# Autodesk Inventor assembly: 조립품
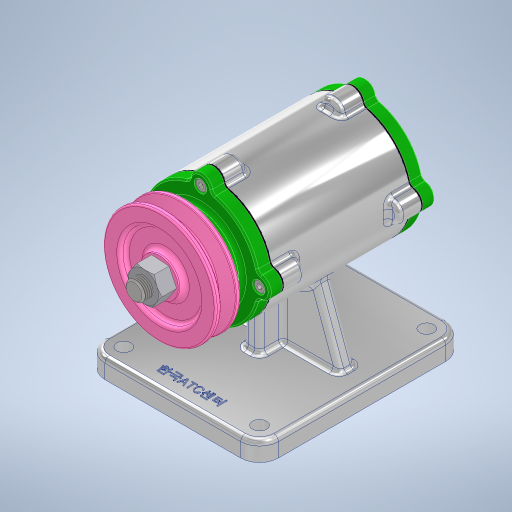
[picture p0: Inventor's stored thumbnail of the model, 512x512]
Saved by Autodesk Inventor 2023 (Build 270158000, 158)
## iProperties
Created: 2023-08
Part Number: 조립품
Document SubType Name: Assembly
Designer: asung
Author: asung
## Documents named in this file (12)
- C:\Users\asung\Desktop\730808V1007\730808V1007\조립품.iam
- C:\Users\asung\Desktop\730808V1007\본체.ipt
- C:\Users\asung\Desktop\730808V1007\730808V1007\앞커버.ipt
- C:\Users\asung\Desktop\730808V1007\730808V1007\뒤커버.ipt
- C:\Users\asung\Desktop\730808V1007\730808V1007\베어링 6204.ipt
- C:\Users\asung\Desktop\730808V1007\730808V1007\개스킷.ipt
- C:\Users\asung\Desktop\730808V1007\730808V1007\오일 실.ipt
- C:\Users\asung\Desktop\730808V1007\730808V1007\축.ipt
- C:\Users\asung\Desktop\730808V1007\730808V1007\키 4 x 4.ipt
- C:\Users\asung\Desktop\730808V1007\730808V1007\볼트 M4 x 12.ipt
- C:\Users\asung\Desktop\730808V1007\730808V1007\V-벨트풀리.ipt
- C:\Users\asung\Desktop\730808V1007\730808V1007\너트 M12 x 1.25.ipt
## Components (8 placed, 6 different names)
1. 개스킷:1
2. 개스킷:2
3. KS B 2023 6204 - 20 x 47 x 14:1
4. KS B 2023 6204 - 20 x 47 x 14:2
5. KS B 1311 (I) 4 x 4 x 12:1
6. KS B 2804 D D - 20 32 8:1
7. V-벨트풀리:1
8. KS B 1012 클래스 1 일반 - 미터 M12x1.25:1
